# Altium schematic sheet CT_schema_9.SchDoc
size 308 x 210 mm
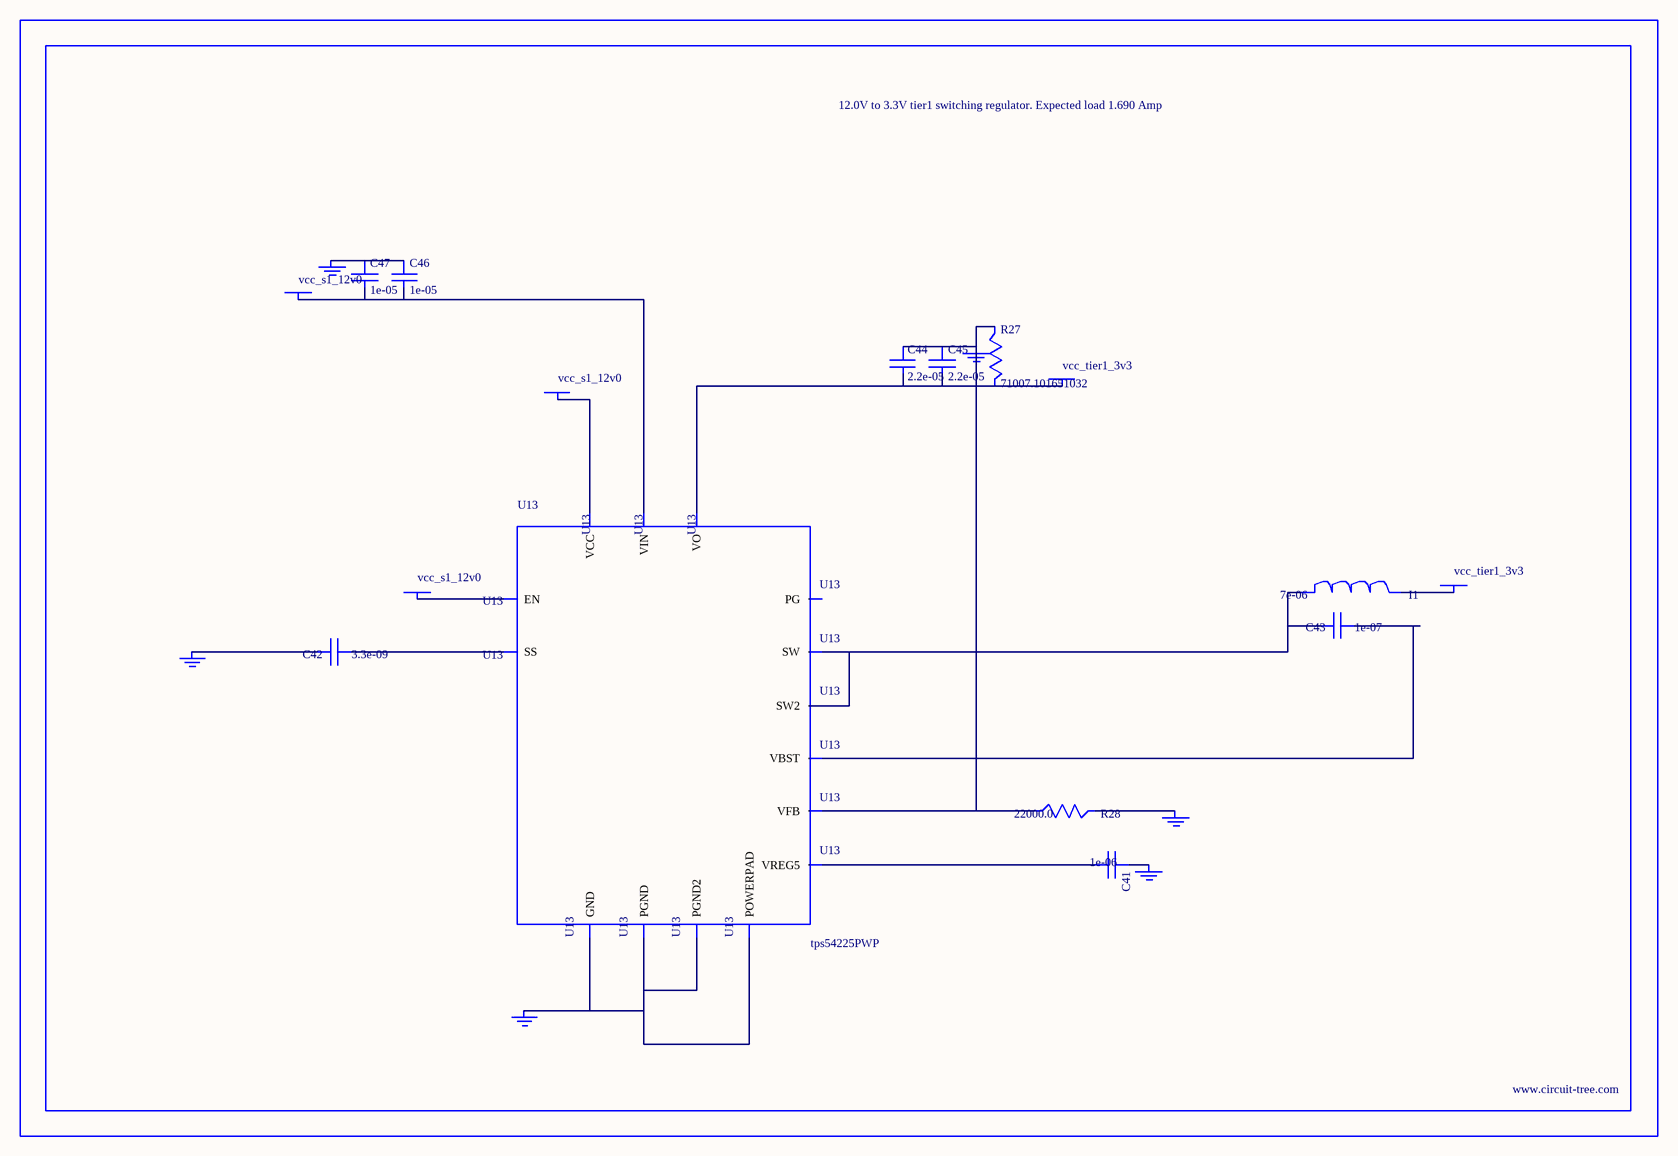
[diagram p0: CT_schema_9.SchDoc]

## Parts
BORDER8  (no value)
C41  1e-06  [C0603]
C42  3.3e-09  [C0402]
C43  1e-07  [C0402]
C44  2.2e-05  [C1210]
C45  2.2e-05  [C1210]
C46  1e-05  [C1206]
C47  1e-05  [C1206]
GND_INSTANCE_8_0  (no value)
GND_INSTANCE_8_1  (no value)
GND_INSTANCE_8_2  (no value)
GND_INSTANCE_8_3  (no value)
GND_INSTANCE_8_4  (no value)
GND_INSTANCE_8_5  (no value)
I1  7e-06  [DR1040]
POWER_INSTANCE_8_0  vcc_tier1_3v3
POWER_INSTANCE_8_1  vcc_s1_12v0
POWER_INSTANCE_8_2  vcc_tier1_3v3
POWER_INSTANCE_8_3  vcc_s1_12v0
POWER_INSTANCE_8_4  vcc_s1_12v0
R27  71007.101651032  [R0603]
R28  22000.0  [R0603]
U13  tps54225PWP  [HTSSOP14]

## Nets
NetC41_1: C41.1 GND_INSTANCE_8_2.0(GND)
NetC41_2: C41.2 U13.3(VREG5)
NetC42_1: C42.1 U13.4(SS)
NetC42_2: C42.2 GND_INSTANCE_8_3.0(GND)
NetC43_1: C43.1 U13.12(VBST)
NetC43_2: C43.2 I1.1 U13.10(SW) U13.11(SW2)
NetC44_1: C44.1 C45.1 GND_INSTANCE_8_0.0(GND) R27.1 R28.1 U13.2(VFB)
NetC44_2: C44.2 C45.2 POWER_INSTANCE_8_0.0(PWR) R27.2 U13.1(VO)
NetC46_1: C46.1 C47.1 GND_INSTANCE_8_5.0(GND)
NetC46_2: C46.2 C47.2 POWER_INSTANCE_8_3.0(PWR) U13.13(VIN)
NetGND_INSTANCE_8_1_0: GND_INSTANCE_8_1.0(GND) R28.2
NetGND_INSTANCE_8_4_0: GND_INSTANCE_8_4.0(GND) U13.5(GND) U13.8(PGND) U13.9(PGND2) U13.15(POWERPAD)
NetI1_2: I1.2 POWER_INSTANCE_8_2.0(PWR)
NetPOWER_INSTANCE_8_1_0: POWER_INSTANCE_8_1.0(PWR) U13.7(EN)
NetPOWER_INSTANCE_8_4_0: POWER_INSTANCE_8_4.0(PWR) U13.14(VCC)

Not connected (* = marked no-connect by the designer): U13 6(PG)

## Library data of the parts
BORDER8 = BORDER_PAGE8
C41 = C0603C105K3RACTU
C42 = C0402C332K3RAC
C43 = C0402C104K3RACTU
C44 C45 = GRM32ER61E226ME15L
C46 C47 = C1206C106K3RACTU
GND_INSTANCE_8_0-GND_INSTANCE_8_5 = GND
I1 = DR1040-7R0-R
POWER_INSTANCE_8_0-POWER_INSTANCE_8_4 = PWR
R27 = R27
R28 = RC0603JR-0722KL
